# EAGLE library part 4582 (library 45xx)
LOOK AHEAD CARRY BLOCK
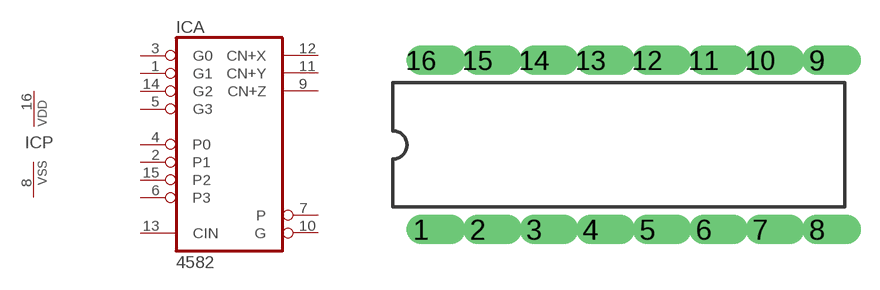
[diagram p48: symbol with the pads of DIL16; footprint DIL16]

Designator prefix IC; gates A=4582 P=PWRN

## 4582N  [DIL16]
1  A:G1  in
2  A:P1  in
3  A:G0  in
4  A:P0  in
5  A:G3  in
6  A:P3  in
7  A:P  out
8  P:VSS  pwr
9  A:CN+Z  out
10  A:G  out
11  A:CN+Y  out
12  A:CN+X  out
13  A:CIN  in
14  A:G2  in
15  A:P2  in
16  P:VDD  pwr

## Footprint DIL16 (pad centres in mm)
Dual In Line
drill 0.813 offset: 1 -8.89,-3.81; 2 -6.35,-3.81; 3 -3.81,-3.81; 4 -1.27,-3.81; 5 1.27,-3.81; 6 3.81,-3.81; 7 6.35,-3.81; 8 8.89,-3.81; 9 8.89,3.81; 10 6.35,3.81; 11 3.81,3.81; 12 1.27,3.81; 13 -1.27,3.81; 14 -3.81,3.81; 15 -6.35,3.81; 16 -8.89,3.81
